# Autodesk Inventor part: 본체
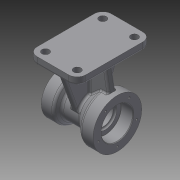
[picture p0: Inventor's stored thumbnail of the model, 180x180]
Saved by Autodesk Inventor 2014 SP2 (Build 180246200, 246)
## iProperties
Created: 2015-08
Part Number: 본체
Material: 일반
Document SubType Name: Modeling
Designer: 이준우
Density: 1 g/cm^3
Appearance: 기본값
Author: 이준우
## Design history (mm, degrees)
sketch "스케치3"
  geometry: L1 (0, 0)-(45, 0); L2 (45, 0)-(45, 40); L3 (45, 40)-(25, 40); L4 (25, 40)-(8.199, 25.903); L5 (0, 0)-(-45, 0); L6 (-45, 0)-(-45, 35); L7 (-45, 35)-(-25, 35); L8 (-25, 35)-(-19.804, 26); L9 (0, 26)-(-19.804, 26); L10 (0, 26)-(8.315, 26)
  constraints: 20 end point, 3 perpendicular, 1 collinear, 1 horizontal, 1 parallel, 1 point on line
  dimensions: "d27" = 45 distance of L1.start L1.end; "d28" = 40 distance of L1.end L2.end; "d29" = 20 distance of L2.end L3.end; "d30" = 45 distance of L1.start L5.end; "d31" = 35 distance of L5.end L6.end; "d32" = 20 distance of L6.end L7.end; "d33" = 26 distance of L1.start L9.start; "d34" = 60 deg angle of L9 L8
revolve "회전1" sketch "스케치3" stored, may be unused: angle "d36" = 90 deg
hole "구멍1" diameter "d39" = 38; stored, may be unused: countersink angle "d43" = 90 deg, drill point angle "d45" = 0 deg; dims "d40" = 6, "d41" = 52, "d42" = 20, "d44" = 23, "d124" = 10, "d125" = 10
hole "구멍2" diameter "d48" = 32; stored, may be unused: countersink angle "d52" = 90 deg, drill point angle "d54" = 0 deg; dims "d49" = 6, "d50" = 40, "d51" = 17, "d53" = 23, "d101" = 10, "d102" = 10
node "작업 평면1"
sketch "스케치4"
  geometry: L1 (40, 0)-(40, 61); L2 (40, 61)-(-40, 61); L3 (-40, 61)-(-40, -61); L4 (-40, -61)-(40, -61); L5 (40, -61)-(40, 0); 1 further point
  constraints: 10 end point, 1 parallel
  dimensions: "d61" = 61 distance of L1.start L1.end; "d62" = 80 distance of L1.end L2.end; "d63" = 122 distance of L2.end L3.end; "d64" = 80 distance of L3.end L4.end
extrude "돌출1" join sketch "스케치4" distance "d65" = 12; taper "d66" = 0 deg
sketch "스케치5"
  geometry: L1 (-40, 61)-(40, 61) reference; L2 (40, -61)-(-40, -61) reference; L3 (-40, -61)-(-40, 61) reference; L4 (40, 61)-(40, -61) reference; L5 (0, 61)-(0, 51); L6 (0, 51)-(-6, 51); L7 (0, 51)-(6, 51); L8 (-40, 0)-(-30, 0); L9 (-30, 0)-(-30, -6); L10 (-30, 0)-(-30, 6); L11 (-74, 0)-(102, 0); L12 (0, -51)-(6, -51); L13 (0, -51)-(-6, -51); L14 (0, 0)-(0, -69); L15 (30, 0)-(30, -6); L16 (30, 0)-(30, 6); L17 (-6, 51)-(-6, -6); L18 (-6, -6)-(-6, -51); L19 (-30, -6)-(-6, -6); L20 (-6, -6)-(30, -6); L21 (-30, 6)-(-6, 6); L22 (-6, 6)-(30, 6); L23 (6, 51)-(6, 6); L24 (6, 6)-(6, -51)
  constraints: 40 end point, 13 perpendicular, 7 parallel, 6 symmetric about line, 2 midpoint, 2 point on line
  dimensions: "d67" = 10 distance of L5.start L5.end; "d68" = 6 distance of L5.end L6.end; "d69" = 6 distance of L5.end L7.end; "d70" = 10 distance of L8.start L8.end; "d71" = 6 distance of L8.end L9.end; "d72" = 6 distance of L8.end L10.end
extrude "돌출2" join sketch "스케치5" stored distance "d73" = 12; taper "d74" = 0 deg
sketch "스케치6"
  geometry: L1 (61, 78)-(-61, 78) reference; L2 (-61, 78)-(-51, 78); L3 (-51, 78)-(-25.091, 6.815); L4 (0, 0)-(0, -77); L5 (51, 78)-(25.091, 6.815); L6 (-51, 78)-(51, 78); C1 r 40 at (0, 0) reference; A1 r 26 centre (0, 0) between (0, -26) and (25.091, 6.815); A2 r 26 centre (0, 0) between (-25.091, 6.815) and (0, -26); A3 r 26 centre (0, 0) between (25.091, 6.815) and (-25.091, 6.815); 1 further point
  constraints: 10 end point, 6 point on circle, 3 centre point, 2 point on line, 2 symmetric about line, 1 coincident, 1 collinear, 1 perpendicular, 2 other
  dimensions: "d75" = 10 distance of L1.end L2.end; "d76" = 70 deg angle of L1 L3
extrude "돌출3" join sketch "스케치6" stored distance "d77" = 10; taper "d78" = 0 deg
sketch "스케치7"
  geometry: L1 (-74, 0)-(-74, 47); L2 (-74, 47)-(79, 47); L3 (0, -68)-(-26, -68); L4 (-26, -68)-(-26, 108); C1 r 6 at (-26, 47); 1 further point
  constraints: 8 end point, 2 perpendicular, 2 point on line, 1 centre point, 1 parallel, 1 vertical
  dimensions: "d80" = 47 distance of L1.start L1.end; "d81" = 26 distance of L3.start L3.end; "d82" = 12 diameter of C1
extrude "돌출4" cut sketch "스케치7" stored distance "d83" = 10; taper "d84" = 0 deg
feature "면 기울기2" dims angle "d86" = 10 deg
sketch "스케치8" dims "d87" = 66
  geometry: 4 further points
  constraints: 1 coincident, 1 horizontal alignment, 2 other
hole "구멍3" sketch "스케치8" at (33, 0) diameter "d88" = 3.242; stored, may be unused: countersink angle "d92" = 90 deg, drill point angle "d94" = 118 deg; dims "d89" = 10, "d90" = 52, "d91" = 20, "d93" = 13
sketch "스케치9" dims "d98" = 54
  geometry: 3 further points
  constraints: 1 coincident, 1 horizontal alignment, 2 other
hole "구멍4" sketch "스케치9" at (-27, 0) diameter "d103" = 3.242; stored, may be unused: countersink angle "d107" = 90 deg, drill point angle "d109" = 118 deg; dims "d104" = 10, "d105" = 52, "d106" = 20, "d108" = 13
sketch "스케치10"
  geometry: L1 (0, 0)-(0, -24); L2 (0, -24)-(119, -24); L3 (78, -61)-(60, -61); L4 (60, -61)-(60, -7); L5 (60, -24)-(54, -24); L6 (60, -18)-(54, -18); L7 (54, -30)-(60, -30); A1 r 6 centre (60, -24) between (60, -30) and (60, -18); A2 r 6 centre (54, -24) between (54, -18) and (54, -30); 1 further point
  constraints: 16 end point, 4 point on circle, 4 tangent, 3 point on line, 2 centre point, 2 parallel, 2 perpendicular, 1 midpoint, 1 vertical
  dimensions: "d114" = 24 distance of L1.start L1.end; "d115" = 18 distance of L3.start L3.end; "d118" = 6 distance of L5.start L5.end; "d119" = 12 diameter of A2
extrude "돌출5" cut sketch "스케치10" stored distance "d120" = 10; taper "d121" = 0 deg
fillet "모깎기1" dims "d122" = 5
fillet "모깎기2" dims "d123" = 0.3
fillet "모깎기3" dims "d126" = 3
fillet "모깎기4" dims "d127" = 14
fillet "모깎기5" dims "d128" = 3
fillet "모깎기6" dims "d129" = 3
fillet "모깎기7" dims "d130" = 3
fillet "모깎기8" dims "d131" = 3
fillet "모깎기9" dims "d132" = 3
fillet "모깎기10" dims "d133" = 3
fillet "모깎기11" dims "d134" = 3
fillet "모깎기12" dims "d135" = 3
fillet "모깎기13" dims "d136" = 3
fillet "모깎기14" dims "d137" = 3
chamfer "모따기1" distance "d138" = 1; stored, may be unused: second distance "d139" = 2, angle "d140" = 45 deg
sketch "스케치11"
  geometry: L1 (6.612, 0.965)-(6.612, 43.965); L2 (6.612, 43.965)-(17.612, 43.965); L3 (17.612, 43.965)-(17.612, 0.965); L4 (17.612, 0.965)-(6.612, 0.965); L5 (-3, 38.132)-(-3, 0) reference; 4 further points
  constraints: 2 midpoint, 1 horizontal alignment, 1 vertical alignment, 2 other
feature "엠보싱1" sketch "스케치11" dims "d27" = 45, "d28" = 40, "d29" = 20, "d30" = 45, "d31" = 35, "d32" = 20, "d33" = 26, "d34" = 60 deg, "d144" = 0.5, "d145" = 0
node "솔리드1"
mirror "대칭1"
mirror "대칭2"
pattern_circular "원형 패턴1" dims angle "d96" = 360 deg
pattern_circular "원형 패턴2" dims angle "d111" = 360 deg
mirror "대칭3"
other parameters: "d35" = 40 deg
